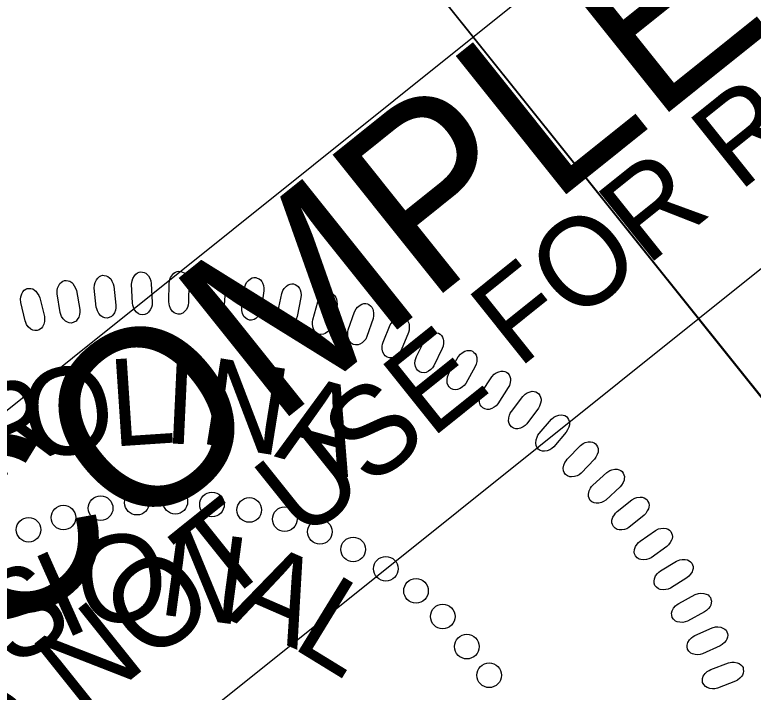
# Model space of a CAD drawing. Extents: x 473546 to 475544, y 505920 to 507827.
# Drawn here: x 474796.9 to 474844.98, y 507638.57 to 507682.65 of the extents above; entities that cross this region are included whole.
import ezdxf

# ---------------------------------------------------------------- set-up
doc = ezdxf.new("R2010")
doc.units = 0
for name, color, linetype in [('Sheet Plan CELL', 7, 'Continuous'), ('Sheet Profile Grid Minor CELL', 7, 'Continuous'), ('Sheet Sticker Exception Certification CELL', 7, 'Continuous'), ('Sheet Sticker Incomplete CELL', 7, 'Continuous')]:
    doc.layers.add(name, color=color, linetype=linetype)

msp = doc.modelspace()

# ---------------------------------------------------------------- linework, layer by layer
at = {"layer": 'Sheet Plan CELL'}
msp.add_line((474806.271, 507706.801), (474876.553, 507619.004), dxfattribs=at)
for points in [[(474806.271, 507706.801), (474884.328, 507769.288), (474954.641, 507681.452), (474876.574, 507618.957)], [(474728.157, 507644.284), (474806.271, 507706.801), (474876.574, 507618.957), (474798.455, 507556.468)]]:
    msp.add_lwpolyline(points, close=True, dxfattribs=at)
at = {"layer": 'Sheet Profile Grid Minor CELL'}
for points in [[(474802.206, 507663.64), (474802.073, 507664.859), (474802.086, 507665.082), (474802.123, 507665.226), (474802.215, 507665.407), (474802.3, 507665.527), (474802.403, 507665.618), (474802.502, 507665.669), (474802.612, 507665.701), (474802.726, 507665.694), (474802.847, 507665.676), (474802.958, 507665.629), (474803.073, 507665.541), (474803.141, 507665.468), (474803.225, 507665.327), (474803.304, 507665.155), (474803.343, 507664.999), (474803.487, 507663.75), (474803.483, 507663.579), (474803.454, 507663.436), (474803.382, 507663.267), (474803.287, 507663.117), (474803.198, 507663.026), (474803.049, 507662.949), (474802.902, 507662.914), (474802.75, 507662.937), (474802.64, 507662.976), (474802.502, 507663.06), (474802.366, 507663.216), (474802.279, 507663.387), (474802.235, 507663.513)], [(474804.563, 507663.896), (474804.506, 507665.121), (474804.533, 507665.342), (474804.579, 507665.484), (474804.683, 507665.659), (474804.775, 507665.772), (474804.883, 507665.857), (474804.987, 507665.902), (474805.098, 507665.928), (474805.21, 507665.913), (474805.331, 507665.888), (474805.438, 507665.833), (474805.548, 507665.739), (474805.611, 507665.662), (474805.685, 507665.515), (474805.753, 507665.339), (474805.783, 507665.18), (474805.849, 507663.925), (474805.834, 507663.755), (474805.795, 507663.613), (474805.714, 507663.45), (474805.608, 507663.305), (474805.514, 507663.221), (474805.361, 507663.154), (474805.212, 507663.127), (474805.061, 507663.16), (474804.954, 507663.205), (474804.822, 507663.299), (474804.695, 507663.463), (474804.62, 507663.639), (474804.584, 507663.767)], [(474806.927, 507663.974), (474806.947, 507665.2), (474806.988, 507665.419), (474807.043, 507665.558), (474807.158, 507665.726), (474807.257, 507665.834), (474807.37, 507665.911), (474807.475, 507665.95), (474807.588, 507665.967), (474807.699, 507665.946), (474807.819, 507665.914), (474807.922, 507665.853), (474808.025, 507665.751), (474808.084, 507665.67), (474808.148, 507665.519), (474808.206, 507665.339), (474808.226, 507665.179), (474808.212, 507663.923), (474808.187, 507663.753), (474808.139, 507663.614), (474808.047, 507663.457), (474807.933, 507663.318), (474807.834, 507663.24), (474807.676, 507663.183), (474807.527, 507663.166), (474807.378, 507663.208), (474807.274, 507663.26), (474807.149, 507663.362), (474807.032, 507663.533), (474806.968, 507663.714), (474806.94, 507663.844)], [(474809.256, 507663.898), (474809.354, 507665.122), (474809.408, 507665.337), (474809.471, 507665.473), (474809.597, 507665.633), (474809.702, 507665.734), (474809.82, 507665.805), (474809.928, 507665.837), (474810.041, 507665.847), (474810.151, 507665.819), (474810.268, 507665.779), (474810.368, 507665.712), (474810.464, 507665.604), (474810.518, 507665.519), (474810.573, 507665.365), (474810.618, 507665.181), (474810.628, 507665.021), (474810.535, 507663.767), (474810.5, 507663.6), (474810.444, 507663.464), (474810.342, 507663.313), (474810.219, 507663.182), (474810.116, 507663.11), (474809.954, 507663.063), (474809.804, 507663.055), (474809.658, 507663.107), (474809.558, 507663.165), (474809.439, 507663.274), (474809.333, 507663.453), (474809.281, 507663.637), (474809.261, 507663.768)], [(474811.676, 507663.667), (474811.85, 507664.881), (474811.918, 507665.092), (474811.99, 507665.224), (474812.125, 507665.375), (474812.236, 507665.47), (474812.358, 507665.533), (474812.468, 507665.558), (474812.582, 507665.562), (474812.69, 507665.526), (474812.805, 507665.48), (474812.9, 507665.406), (474812.989, 507665.292), (474813.037, 507665.204), (474813.082, 507665.047), (474813.116, 507664.861), (474813.116, 507664.7), (474812.944, 507663.455), (474812.899, 507663.29), (474812.834, 507663.158), (474812.723, 507663.013), (474812.592, 507662.891), (474812.484, 507662.825), (474812.321, 507662.788), (474812.17, 507662.79), (474812.028, 507662.85), (474811.931, 507662.915), (474811.819, 507663.031), (474811.725, 507663.216), (474811.684, 507663.404), (474811.673, 507663.536)], [(474799.859, 507663.279), (474799.649, 507664.488), (474799.648, 507664.71), (474799.676, 507664.857), (474799.757, 507665.043), (474799.834, 507665.168), (474799.931, 507665.266), (474800.027, 507665.323), (474800.134, 507665.362), (474800.248, 507665.361), (474800.371, 507665.352), (474800.485, 507665.311), (474800.605, 507665.231), (474800.677, 507665.162), (474800.769, 507665.027), (474800.859, 507664.86), (474800.909, 507664.707), (474801.131, 507663.47), (474801.137, 507663.299), (474801.117, 507663.154), (474801.057, 507662.981), (474800.97, 507662.824), (474800.888, 507662.729), (474800.743, 507662.643), (474800.599, 507662.598), (474800.445, 507662.611), (474800.333, 507662.643), (474800.191, 507662.72), (474800.044, 507662.866), (474799.947, 507663.031), (474799.895, 507663.154)], [(474814.026, 507663.31), (474814.276, 507664.511), (474814.357, 507664.719), (474814.437, 507664.845), (474814.581, 507664.988), (474814.699, 507665.076), (474814.825, 507665.131), (474814.935, 507665.148), (474815.049, 507665.146), (474815.155, 507665.103), (474815.266, 507665.049), (474815.356, 507664.969), (474815.438, 507664.85), (474815.481, 507664.76), (474815.516, 507664.599), (474815.538, 507664.412), (474815.527, 507664.251), (474815.279, 507663.019), (474815.222, 507662.858), (474815.15, 507662.73), (474815.03, 507662.593), (474814.891, 507662.478), (474814.78, 507662.42), (474814.614, 507662.393), (474814.464, 507662.405), (474814.326, 507662.474), (474814.233, 507662.544), (474814.129, 507662.667), (474814.047, 507662.858), (474814.017, 507663.048), (474814.014, 507663.18)], [(474797.566, 507662.745), (474797.281, 507663.938), (474797.266, 507664.16), (474797.284, 507664.308), (474797.354, 507664.499), (474797.423, 507664.628), (474797.514, 507664.732), (474797.606, 507664.795), (474797.711, 507664.841), (474797.824, 507664.847), (474797.947, 507664.846), (474798.063, 507664.812), (474798.188, 507664.739), (474798.265, 507664.676), (474798.365, 507664.545), (474798.465, 507664.385), (474798.524, 507664.235), (474798.824, 507663.015), (474798.841, 507662.845), (474798.83, 507662.698), (474798.78, 507662.522), (474798.703, 507662.36), (474798.627, 507662.26), (474798.489, 507662.165), (474798.348, 507662.111), (474798.194, 507662.115), (474798.08, 507662.139), (474797.933, 507662.207), (474797.778, 507662.344), (474797.67, 507662.503), (474797.611, 507662.622)], [(474816.305, 507662.8), (474816.63, 507663.983), (474816.724, 507664.184), (474816.811, 507664.305), (474816.964, 507664.44), (474817.087, 507664.519), (474817.216, 507664.566), (474817.328, 507664.577), (474817.441, 507664.567), (474817.544, 507664.518), (474817.651, 507664.457), (474817.736, 507664.372), (474817.811, 507664.248), (474817.848, 507664.155), (474817.873, 507663.993), (474817.883, 507663.804), (474817.863, 507663.645), (474817.537, 507662.431), (474817.47, 507662.274), (474817.39, 507662.15), (474817.262, 507662.021), (474817.116, 507661.915), (474817.001, 507661.864), (474816.834, 507661.848), (474816.685, 507661.868), (474816.551, 507661.946), (474816.464, 507662.022), (474816.367, 507662.152), (474816.297, 507662.347), (474816.279, 507662.538), (474816.285, 507662.671)], [(474818.615, 507662.156), (474819.013, 507663.316), (474819.12, 507663.512), (474819.214, 507663.627), (474819.375, 507663.751), (474819.503, 507663.823), (474819.634, 507663.862), (474819.747, 507663.866), (474819.859, 507663.848), (474819.959, 507663.793), (474820.062, 507663.726), (474820.141, 507663.635), (474820.208, 507663.506), (474820.239, 507663.412), (474820.254, 507663.248), (474820.252, 507663.059), (474820.222, 507662.901), (474819.821, 507661.71), (474819.744, 507661.557), (474819.656, 507661.44), (474819.52, 507661.318), (474819.368, 507661.222), (474819.251, 507661.178), (474819.083, 507661.172), (474818.935, 507661.202), (474818.807, 507661.288), (474818.724, 507661.37), (474818.636, 507661.506), (474818.578, 507661.704), (474818.573, 507661.896), (474818.586, 507662.029)], [(474820.88, 507661.343), (474821.35, 507662.476), (474821.469, 507662.664), (474821.57, 507662.773), (474821.739, 507662.887), (474821.871, 507662.951), (474822.005, 507662.982), (474822.117, 507662.978), (474822.228, 507662.954), (474822.324, 507662.892), (474822.423, 507662.819), (474822.497, 507662.724), (474822.556, 507662.591), (474822.58, 507662.495), (474822.585, 507662.331), (474822.571, 507662.142), (474822.531, 507661.986), (474822.056, 507660.823), (474821.97, 507660.675), (474821.875, 507660.563), (474821.731, 507660.45), (474821.574, 507660.364), (474821.453, 507660.327), (474821.286, 507660.332), (474821.14, 507660.371), (474821.017, 507660.465), (474820.939, 507660.552), (474820.86, 507660.693), (474820.815, 507660.895), (474820.822, 507661.087), (474820.844, 507661.218)], [(474823.046, 507660.409), (474823.586, 507661.51), (474823.717, 507661.69), (474823.825, 507661.793), (474824.001, 507661.896), (474824.136, 507661.951), (474824.272, 507661.974), (474824.383, 507661.963), (474824.493, 507661.932), (474824.585, 507661.864), (474824.679, 507661.784), (474824.747, 507661.685), (474824.796, 507661.549), (474824.815, 507661.451), (474824.81, 507661.287), (474824.784, 507661.1), (474824.734, 507660.947), (474824.187, 507659.815), (474824.092, 507659.673), (474823.99, 507659.567), (474823.84, 507659.464), (474823.677, 507659.388), (474823.555, 507659.359), (474823.387, 507659.375), (474823.244, 507659.423), (474823.128, 507659.524), (474823.056, 507659.615), (474822.985, 507659.761), (474822.953, 507659.966), (474822.972, 507660.157), (474823.003, 507660.286)], [(474825.161, 507659.333), (474825.77, 507660.399), (474825.911, 507660.57), (474826.025, 507660.666), (474826.207, 507660.758), (474826.346, 507660.804), (474826.483, 507660.818), (474826.594, 507660.801), (474826.701, 507660.763), (474826.788, 507660.689), (474826.877, 507660.604), (474826.938, 507660.501), (474826.98, 507660.361), (474826.992, 507660.263), (474826.976, 507660.099), (474826.939, 507659.914), (474826.879, 507659.765), (474826.262, 507658.67), (474826.159, 507658.534), (474826.051, 507658.435), (474825.894, 507658.341), (474825.727, 507658.275), (474825.603, 507658.254), (474825.437, 507658.28), (474825.297, 507658.337), (474825.187, 507658.446), (474825.121, 507658.541), (474825.06, 507658.69), (474825.041, 507658.897), (474825.071, 507659.086), (474825.11, 507659.214)], [(474827.289, 507658.073), (474827.964, 507659.098), (474828.116, 507659.26), (474828.236, 507659.349), (474828.423, 507659.428), (474828.565, 507659.467), (474828.702, 507659.472), (474828.811, 507659.448), (474828.916, 507659.402), (474828.999, 507659.324), (474829.082, 507659.233), (474829.136, 507659.126), (474829.169, 507658.985), (474829.176, 507658.886), (474829.149, 507658.723), (474829.101, 507658.541), (474829.032, 507658.395), (474828.347, 507657.341), (474828.235, 507657.212), (474828.121, 507657.12), (474827.959, 507657.036), (474827.788, 507656.981), (474827.663, 507656.968), (474827.499, 507657.004), (474827.363, 507657.07), (474827.26, 507657.185), (474827.2, 507657.284), (474827.149, 507657.438), (474827.142, 507657.644), (474827.184, 507657.832), (474827.231, 507657.957)], [(474829.229, 507656.842), (474829.967, 507657.822), (474830.128, 507657.974), (474830.253, 507658.055), (474830.445, 507658.124), (474830.589, 507658.153), (474830.726, 507658.149), (474830.834, 507658.118), (474830.936, 507658.066), (474831.014, 507657.983), (474831.091, 507657.887), (474831.138, 507657.777), (474831.162, 507657.634), (474831.162, 507657.534), (474831.126, 507657.374), (474831.066, 507657.194), (474830.988, 507657.054), (474830.238, 507656.045), (474830.119, 507655.923), (474829.999, 507655.838), (474829.831, 507655.765), (474829.658, 507655.72), (474829.532, 507655.715), (474829.371, 507655.762), (474829.239, 507655.836), (474829.144, 507655.958), (474829.09, 507656.06), (474829.049, 507656.216), (474829.055, 507656.423), (474829.109, 507656.607), (474829.163, 507656.729)], [(474831.035, 507655.4), (474831.833, 507656.332), (474832.004, 507656.474), (474832.134, 507656.547), (474832.33, 507656.603), (474832.475, 507656.623), (474832.613, 507656.611), (474832.717, 507656.573), (474832.816, 507656.515), (474832.888, 507656.427), (474832.959, 507656.326), (474833, 507656.213), (474833.014, 507656.07), (474833.009, 507655.97), (474832.962, 507655.812), (474832.891, 507655.637), (474832.804, 507655.501), (474831.993, 507654.541), (474831.865, 507654.427), (474831.741, 507654.351), (474831.569, 507654.288), (474831.393, 507654.255), (474831.268, 507654.257), (474831.109, 507654.313), (474830.982, 507654.396), (474830.895, 507654.523), (474830.848, 507654.629), (474830.816, 507654.787), (474830.836, 507654.994), (474830.901, 507655.175), (474830.963, 507655.292)], [(474832.87, 507653.745), (474833.725, 507654.624), (474833.904, 507654.756), (474834.039, 507654.82), (474834.238, 507654.864), (474834.384, 507654.875), (474834.52, 507654.854), (474834.623, 507654.81), (474834.717, 507654.746), (474834.784, 507654.653), (474834.849, 507654.548), (474834.883, 507654.433), (474834.888, 507654.288), (474834.875, 507654.19), (474834.819, 507654.035), (474834.737, 507653.864), (474834.642, 507653.734), (474833.772, 507652.827), (474833.638, 507652.722), (474833.508, 507652.653), (474833.333, 507652.601), (474833.155, 507652.579), (474833.03, 507652.589), (474832.875, 507652.655), (474832.754, 507652.746), (474832.675, 507652.878), (474832.635, 507652.987), (474832.613, 507653.147), (474832.645, 507653.352), (474832.722, 507653.527), (474832.791, 507653.641)], [(474834.538, 507652.051), (474835.446, 507652.875), (474835.634, 507652.994), (474835.772, 507653.05), (474835.973, 507653.081), (474836.12, 507653.083), (474836.254, 507653.053), (474836.354, 507653.003), (474836.444, 507652.933), (474836.505, 507652.837), (474836.563, 507652.728), (474836.589, 507652.611), (474836.586, 507652.466), (474836.567, 507652.368), (474836.502, 507652.218), (474836.409, 507652.052), (474836.306, 507651.929), (474835.38, 507651.078), (474835.24, 507650.981), (474835.106, 507650.921), (474834.928, 507650.88), (474834.749, 507650.869), (474834.625, 507650.887), (474834.475, 507650.963), (474834.359, 507651.06), (474834.289, 507651.198), (474834.255, 507651.309), (474834.244, 507651.47), (474834.289, 507651.672), (474834.376, 507651.843), (474834.452, 507651.952)], [(474836.111, 507650.324), (474837.069, 507651.091), (474837.263, 507651.198), (474837.405, 507651.245), (474837.608, 507651.263), (474837.754, 507651.256), (474837.886, 507651.218), (474837.982, 507651.161), (474838.068, 507651.086), (474838.123, 507650.986), (474838.174, 507650.874), (474838.193, 507650.755), (474838.18, 507650.611), (474838.155, 507650.514), (474838.08, 507650.368), (474837.978, 507650.209), (474837.867, 507650.092), (474836.89, 507649.301), (474836.744, 507649.213), (474836.607, 507649.161), (474836.426, 507649.131), (474836.247, 507649.132), (474836.124, 507649.158), (474835.979, 507649.243), (474835.871, 507649.347), (474835.808, 507649.489), (474835.782, 507649.602), (474835.78, 507649.763), (474835.838, 507649.963), (474835.936, 507650.127), (474836.019, 507650.232)], [(474837.61, 507648.398), (474838.614, 507649.103), (474838.815, 507649.197), (474838.959, 507649.235), (474839.163, 507649.241), (474839.309, 507649.225), (474839.438, 507649.179), (474839.53, 507649.116), (474839.612, 507649.035), (474839.659, 507648.932), (474839.704, 507648.817), (474839.715, 507648.697), (474839.693, 507648.554), (474839.662, 507648.46), (474839.578, 507648.318), (474839.466, 507648.166), (474839.348, 507648.056), (474838.324, 507647.328), (474838.172, 507647.25), (474838.032, 507647.206), (474837.85, 507647.188), (474837.671, 507647.2), (474837.55, 507647.233), (474837.411, 507647.327), (474837.308, 507647.439), (474837.256, 507647.584), (474837.236, 507647.698), (474837.245, 507647.859), (474837.315, 507648.054), (474837.424, 507648.213), (474837.512, 507648.311)], [(474838.942, 507646.467), (474839.989, 507647.107), (474840.195, 507647.19), (474840.341, 507647.218), (474840.545, 507647.212), (474840.689, 507647.186), (474840.815, 507647.131), (474840.904, 507647.063), (474840.98, 507646.977), (474841.021, 507646.872), (474841.058, 507646.754), (474841.062, 507646.634), (474841.031, 507646.492), (474840.994, 507646.4), (474840.902, 507646.264), (474840.78, 507646.12), (474840.655, 507646.017), (474839.587, 507645.355), (474839.431, 507645.285), (474839.288, 507645.251), (474839.106, 507645.244), (474838.928, 507645.267), (474838.809, 507645.308), (474838.676, 507645.411), (474838.581, 507645.528), (474838.537, 507645.677), (474838.525, 507645.792), (474838.543, 507645.952), (474838.626, 507646.142), (474838.744, 507646.294), (474838.839, 507646.387)], [(474840.124, 507644.356), (474841.208, 507644.928), (474841.419, 507644.998), (474841.567, 507645.018), (474841.77, 507644.997), (474841.912, 507644.962), (474842.035, 507644.901), (474842.119, 507644.827), (474842.19, 507644.737), (474842.224, 507644.629), (474842.253, 507644.509), (474842.25, 507644.388), (474842.21, 507644.249), (474842.168, 507644.159), (474842.067, 507644.03), (474841.936, 507643.893), (474841.806, 507643.799), (474840.698, 507643.205), (474840.537, 507643.145), (474840.393, 507643.12), (474840.21, 507643.125), (474840.034, 507643.159), (474839.918, 507643.207), (474839.792, 507643.318), (474839.705, 507643.441), (474839.67, 507643.592), (474839.665, 507643.708), (474839.694, 507643.866), (474839.788, 507644.051), (474839.916, 507644.195), (474840.016, 507644.281)], [(474841.185, 507642.26), (474842.303, 507642.764), (474842.518, 507642.819), (474842.667, 507642.83), (474842.868, 507642.797), (474843.008, 507642.753), (474843.127, 507642.683), (474843.206, 507642.605), (474843.27, 507642.51), (474843.298, 507642.401), (474843.32, 507642.279), (474843.309, 507642.159), (474843.26, 507642.023), (474843.212, 507641.935), (474843.103, 507641.812), (474842.965, 507641.684), (474842.828, 507641.598), (474841.686, 507641.075), (474841.521, 507641.026), (474841.376, 507641.01), (474841.194, 507641.026), (474841.02, 507641.071), (474840.908, 507641.126), (474840.789, 507641.245), (474840.709, 507641.373), (474840.684, 507641.526), (474840.687, 507641.642), (474840.725, 507641.799), (474840.831, 507641.977), (474840.967, 507642.113), (474841.073, 507642.192)], [(474842.216, 507640.054), (474843.365, 507640.487), (474843.583, 507640.529), (474843.732, 507640.53), (474843.93, 507640.485), (474844.067, 507640.433), (474844.182, 507640.355), (474844.256, 507640.272), (474844.313, 507640.174), (474844.334, 507640.062), (474844.349, 507639.939), (474844.33, 507639.821), (474844.273, 507639.687), (474844.22, 507639.603), (474844.103, 507639.488), (474843.957, 507639.368), (474843.815, 507639.291), (474842.642, 507638.841), (474842.475, 507638.802), (474842.329, 507638.795), (474842.148, 507638.822), (474841.978, 507638.878), (474841.869, 507638.941), (474841.758, 507639.067), (474841.686, 507639.2), (474841.671, 507639.353), (474841.681, 507639.469), (474841.729, 507639.623), (474841.846, 507639.795), (474841.99, 507639.921), (474842.1, 507639.994)]]:
    msp.add_lwpolyline(points, close=True, dxfattribs=at)
for centre in [(474804.849, 507650.908), (474807.349, 507650.97), (474802.486, 507650.549), (474809.737, 507650.788), (474812.163, 507650.433), (474800.067, 507649.94), (474814.477, 507649.835), (474797.797, 507649.145), (474816.766, 507649.013), (474818.93, 507647.864), (474821.057, 507646.607), (474823.023, 507645.169), (474824.764, 507643.501), (474826.332, 507641.541), (474827.786, 507639.677)]:
    msp.add_circle(centre, 0.801, dxfattribs=at)
at = {"layer": 'Sheet Sticker Incomplete CELL'}
msp.add_lwpolyline([(474784.034, 507616.957), (474769.35, 507635.305), (474884.119, 507727.158), (474898.803, 507708.81)], close=True, dxfattribs=at)

# ---------------------------------------------------------------- texts
at = {"layer": 'Sheet Profile Grid Minor CELL'}
for s, rotation, p in [('L', 3.8121, (474803.234, 507654.549)), ('I', 357.3228, (474806.494, 507654.785)), ('N', 350.8334, (474808.791, 507654.804)), ('O', 10.3015, (474797.957, 507653.568)), ('R', 23.2802, (474795.241, 507652.232)), ('A', 344.344, (474813.745, 507653.927)), ('O', 8.2011, (474801.33, 507642.77)), ('N', 352.3215, (474806.137, 507643.665)), ('I', 24.0807, (474800.049, 507641.964)), ('A', 336.4419, (474810.667, 507643.345)), ('S', 32.0205, (474796.687, 507640.083)), ('L', 328.5021, (474814.821, 507641.553))]:
    msp.add_text(s, height=5.669, rotation=rotation, dxfattribs=at).set_placement(p)
at = {"layer": 'Sheet Sticker Exception Certification CELL'}
for s, p in [('DOCUMENT NOT CONSIDERED FINAL', (474821.37, 507561.557)), ('DOCUMENT NOT CONSIDERED FINAL', (474821.37, 507561.557)), ('UNLESS ALL SIGNATURES COMPLETED', (474822.91, 507551.518)), ('UNLESS ALL SIGNATURES COMPLETED', (474822.91, 507551.518))]:
    msp.add_text(s, height=5.5, rotation=38.6712, dxfattribs=at).set_placement(p)
at = {"layer": 'Sheet Sticker Incomplete CELL'}
for s, height, p in [('INCOMPLETE PLANS', 11.52, (474783.711, 507631.684)), ('DO NOT USE FOR R/W ACQUISITION', 5.76, (474790.591, 507628.289))]:
    msp.add_text(s, height=height, rotation=38.6712, dxfattribs=at).set_placement(p)

doc.saveas('drawing.dxf')
